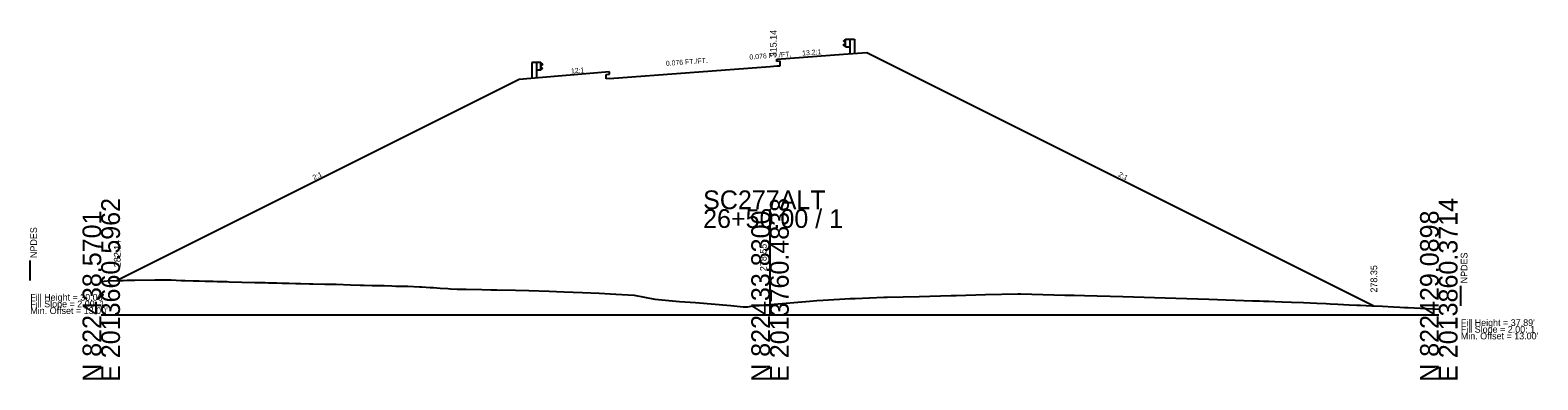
# Model space of a CAD drawing. Extents: x 205929 to 2357175, y -1785700 to 827636.
# Drawn here: x 2017409.5 to 2017635, y 824534.6 to 824586.8 of the extents above; entities that cross this region are included whole.
import ezdxf

# ---------------------------------------------------------------- set-up
doc = ezdxf.new("R2010")
doc.units = 0
for name, color, linetype in [('RD_GPK_XS_Cell', 7, 'Continuous'), ('RD_XS_Base', 7, 'Continuous'), ('RD_XS_EarthShd', 7, 'Continuous'), ('RD_XS_ExGround', 7, 'Continuous'), ('RD_XS_GR', 7, 'Continuous'), ('RD_XS_NPDES', 7, 'Continuous'), ('RD_XS_Pave', 7, 'Continuous'), ('RD_XS_TieSlope', 7, 'Continuous'), ('RD_XS_TX_Elev_EX', 7, 'Continuous'), ('RD_XS_TX_Elev_PR', 7, 'Continuous'), ('RD_XS_TX_ShdSlope', 7, 'Continuous'), ('RD_XS_TX_Slope', 7, 'Continuous'), ('RD_XS_TX_Warning', 7, 'Continuous')]:
    doc.layers.add(name, color=color, linetype=linetype)

msp = doc.modelspace()

# ---------------------------------------------------------------- linework, layer by layer
at = {"layer": 'RD_GPK_XS_Cell'}
for p, q in [((2017520.17, 824544.26), (2017520.17, 824560.07)), ((2017420.17, 824544.26), (2017520.17, 824544.26)), ((2017520.17, 824544.26), (2017620.17, 824544.26))]:
    msp.add_line(p, q, dxfattribs=at)
at = {"layer": 'RD_XS_Base'}
for p, q in [((2017496.17, 824579.58), (2017520.17, 824581.4)), ((2017520.17, 824581.4), (2017521.17, 824581.48))]:
    msp.add_line(p, q, dxfattribs=at)
at = {"layer": 'RD_XS_EarthShd'}
for p, q in [((2017521.17, 824582.48), (2017531.17, 824583.23)), ((2017531.17, 824583.23), (2017534.67, 824583.5)), ((2017486.17, 824579.75), (2017482.67, 824579.46)), ((2017496.17, 824580.58), (2017486.17, 824579.75))]:
    msp.add_line(p, q, dxfattribs=at)
at = {"layer": 'RD_XS_ExGround'}
msp.add_lwpolyline([(2017420.17, 824549.25), (2017421.04, 824549.34), (2017423.08, 824549.42), (2017423.45, 824549.43), (2017424.05, 824549.44), (2017425.18, 824549.46), (2017428.16, 824549.51), (2017428.73, 824549.53), (2017430.62, 824549.49), (2017432.14, 824549.42), (2017432.71, 824549.41), (2017433.93, 824549.37), (2017434.8, 824549.35), (2017435.72, 824549.33), (2017436.9, 824549.29), (2017437.52, 824549.28), (2017438.98, 824549.24), (2017439.3, 824549.23), (2017441.19, 824549.18), (2017443.13, 824549.13), (2017444.67, 824549.09), (2017445.17, 824549.08), (2017446.45, 824549.05), (2017447.21, 824549.03), (2017448.23, 824549), (2017449.25, 824548.98), (2017450.02, 824548.96), (2017451.3, 824548.93), (2017451.81, 824548.92), (2017453.59, 824548.88), (2017455.3, 824548.84), (2017457.44, 824548.77), (2017458.91, 824548.73), (2017459.5, 824548.71), (2017460.69, 824548.68), (2017461.56, 824548.66), (2017462.47, 824548.64), (2017463.62, 824548.6), (2017464.24, 824548.58), (2017465.67, 824548.55), (2017466.01, 824548.54), (2017467.78, 824548.48), (2017468.11, 824548.47), (2017469.34, 824548.38), (2017469.85, 824548.35), (2017470.87, 824548.28), (2017471.99, 824548.2), (2017472.39, 824548.17), (2017473.38, 824548.12), (2017473.7, 824548.11), (2017474.73, 824548.09), (2017477.1, 824548.04), (2017478.44, 824548.01), (2017479.3, 824548), (2017482.13, 824547.96), (2017484.1, 824547.9), (2017487.13, 824547.82), (2017489.35, 824547.74), (2017492.14, 824547.63), (2017494.61, 824547.52), (2017497.14, 824547.38), (2017499.86, 824547.21), (2017502.95, 824546.63), (2017506.64, 824546.27), (2017509.01, 824546.14), (2017514.33, 824545.66), (2017516.16, 824545.45), (2017516.84, 824545.48), (2017517.33, 824545.57), (2017518.55, 824545.69), (2017519.41, 824545.76), (2017520.17, 824545.81), (2017526.14, 824546.33), (2017527.18, 824546.4), (2017528.12, 824546.46), (2017532.18, 824546.7), (2017532.9, 824546.73), (2017537.19, 824546.91), (2017537.68, 824546.91), (2017542.46, 824547.03), (2017547.24, 824547.15), (2017548.02, 824547.18), (2017552.41, 824547.34), (2017557.21, 824547.44), (2017557.67, 824547.43), (2017564.24, 824547.24), (2017564.84, 824547.21), (2017565.63, 824547.2), (2017567.21, 824547.18), (2017572.91, 824547.01), (2017580.84, 824546.77), (2017585.78, 824546.64), (2017592.33, 824546.39), (2017592.8, 824546.37), (2017593.34, 824546.35), (2017593.98, 824546.32), (2017594.74, 824546.3), (2017595.64, 824546.26), (2017596.75, 824546.22), (2017598.15, 824546.16), (2017599.94, 824546.11), (2017601.94, 824546.01), (2017603.34, 824545.95), (2017603.92, 824545.92), (2017605.05, 824545.86), (2017605.93, 824545.82), (2017606.76, 824545.78), (2017607.92, 824545.73), (2017608.47, 824545.7), (2017610.17, 824545.62), (2017611.75, 824545.55), (2017613.38, 824545.45), (2017614.35, 824545.43), (2017615.05, 824545.39), (2017615.57, 824545.36), (2017620.17, 824545.14)], dxfattribs=at)
at = {"layer": 'RD_XS_GR'}
for p, q in [((2017531.44, 824585.41), (2017531.17, 824585.21)), ((2017531.17, 824585.21), (2017531.17, 824585.16)), ((2017531.17, 824585.16), (2017531.44, 824584.96)), ((2017531.44, 824584.32), (2017531.44, 824585.48)), ((2017531.44, 824585.48), (2017532.11, 824585.48)), ((2017532.11, 824585.48), (2017532.11, 824583.3)), ((2017532.11, 824585.48), (2017532.78, 824585.48)), ((2017532.78, 824585.48), (2017532.78, 824583.36)), ((2017531.17, 824584.64), (2017531.44, 824584.84)), ((2017531.17, 824584.59), (2017531.17, 824584.64)), ((2017531.44, 824584.39), (2017531.17, 824584.59)), ((2017531.44, 824584.32), (2017532.11, 824584.32)), ((2017484.57, 824582), (2017484.57, 824579.61)), ((2017485.24, 824582), (2017484.57, 824582)), ((2017485.24, 824582), (2017485.24, 824579.67)), ((2017485.9, 824582), (2017485.24, 824582)), ((2017485.9, 824580.83), (2017485.24, 824580.83)), ((2017485.9, 824580.83), (2017485.9, 824582)), ((2017485.9, 824581.92), (2017486.17, 824581.72)), ((2017486.17, 824581.67), (2017485.9, 824581.47)), ((2017486.17, 824581.15), (2017485.9, 824581.35)), ((2017485.9, 824580.9), (2017486.17, 824581.1)), ((2017486.17, 824581.72), (2017486.17, 824581.67)), ((2017486.17, 824581.1), (2017486.17, 824581.15))]:
    msp.add_line(p, q, dxfattribs=at)
at = {"layer": 'RD_XS_NPDES'}
for p, q in [((2017409.56, 824549.4), (2017409.56, 824552.4)), ((2017623.46, 824545.61), (2017623.46, 824548.61))]:
    msp.add_line(p, q, dxfattribs=at)
at = {"layer": 'RD_XS_Pave'}
for p, q in [((2017521.17, 824582.15), (2017521.17, 824582.48)), ((2017521.67, 824582.18), (2017521.17, 824582.15)), ((2017521.17, 824581.48), (2017521.67, 824581.51)), ((2017521.67, 824581.51), (2017521.67, 824582.18)), ((2017495.67, 824580.21), (2017496.17, 824580.25)), ((2017495.67, 824579.54), (2017495.67, 824580.21)), ((2017496.17, 824579.58), (2017495.67, 824579.54)), ((2017496.17, 824580.25), (2017496.17, 824580.58))]:
    msp.add_line(p, q, dxfattribs=at)
at = {"layer": 'RD_XS_TieSlope'}
for p, q in [((2017534.67, 824583.5), (2017610.46, 824545.61)), ((2017482.67, 824579.46), (2017422.56, 824549.4))]:
    msp.add_line(p, q, dxfattribs=at)

# ---------------------------------------------------------------- texts
at = {"layer": 'RD_GPK_XS_Cell'}
for s, p in [('SC277ALT', (2017510.17, 824560.07)), ('26+50.00 / 1', (2017510.17, 824557.27))]:
    msp.add_text(s, height=2.8, dxfattribs=at).set_placement(p)
for s, p in [('E 2013660.5962', (2017422.97, 824534.26)), ('E 2013760.4838', (2017522.97, 824534.26)), ('E 2013860.3714', (2017622.97, 824534.26)), ('N 822438.5701', (2017420.17, 824534.26)), ('N 822433.8300', (2017520.17, 824534.26)), ('N 822429.0898', (2017620.17, 824534.26))]:
    msp.add_text(s, height=2.8, rotation=90, dxfattribs=at).set_placement(p)
at = {"layer": 'RD_XS_TX_Elev_EX'}
msp.add_text('278.55', height=1, rotation=90, dxfattribs=at).set_placement((2017519.67, 824550.81))
at = {"layer": 'RD_XS_TX_Elev_PR'}
for s, p in [(' 315.14', (2017521.17, 824582.4)), ('282.14', (2017423.06, 824551.4)), ('278.35', (2017610.96, 824547.61))]:
    msp.add_text(s, height=1, rotation=90, dxfattribs=at).set_placement(p)
at = {"layer": 'RD_XS_TX_ShdSlope'}
for s, rotation, p in [('13.2:1', 4.3347, (2017525, 824583.02)), ('12:1', 4.7636, (2017490.44, 824580.35))]:
    msp.add_text(s, height=0.75, rotation=rotation, dxfattribs=at).set_placement(p)
at = {"layer": 'RD_XS_TX_Slope'}
for s, rotation, p in [('0.076 FT./FT.', 4.3347, (2017517.12, 824582.42)), ('0.076 FT./FT.', 4.3347, (2017504.62, 824581.47)), ('2:1', 26.5651, (2017452, 824564.4)), ('2:1', 333.4349, (2017572.17, 824565.03))]:
    msp.add_text(s, height=0.75, rotation=rotation, dxfattribs=at).set_placement(p)
at = {"layer": 'RD_XS_TX_Warning'}
for p in [(2017410.56, 824552.4), (2017624.46, 824548.61)]:
    msp.add_text(' NPDES', height=1, rotation=90, dxfattribs=at).set_placement(p)
for s, p in [("Fill Height = 30.06' ", (2017409.56, 824546.4)), ('Fill Slope = 2.00: 1', (2017409.56, 824545.4)), ("Min. Offset = 13.00' ", (2017409.56, 824544.4)), ("Fill Height = 37.89' ", (2017623.46, 824542.61)), ('Fill Slope = 2.00: 1', (2017623.46, 824541.61)), ("Min. Offset = 13.00' ", (2017623.46, 824540.61))]:
    msp.add_text(s, height=1, dxfattribs=at).set_placement(p)

doc.saveas('drawing.dxf')
